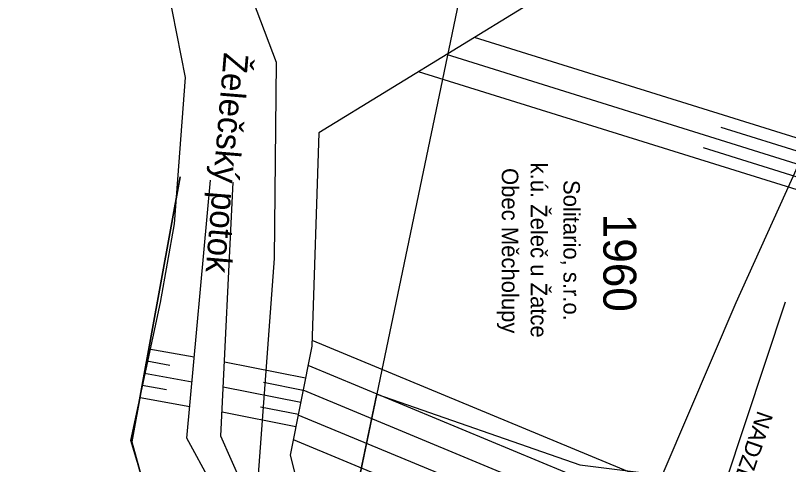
# Model space of a CAD drawing. Extents: x -801372 to -800991, y -1017235 to -1016862.
# Drawn here: x -801166.43 to -801119.55, y -1017024.1 to -1016996.85 of the extents above; entities that cross this region are included whole.
import ezdxf

# ---------------------------------------------------------------- set-up
doc = ezdxf.new("R2010")
doc.units = 0
for name, color, linetype in [('09 - stávající terén', 7, 'Continuous'), ('15 - popisy', 7, 'Continuous'), ('19 - katastr', 7, 'Continuous'), ('19b - katastr - hranice SŽDC', 7, 'Continuous'), ('19b - katastr popisy', 7, 'Continuous'), ('26 - obvod_stavby', 7, 'Continuous'), ('27 - dočasné zábory', 7, 'Continuous'), ('Vrstva 17', 7, 'Continuous'), ('Vrstva 25', 7, 'Continuous'), ('Vrstva 48 - svahy', 7, 'Continuous'), ('Vrstva 58', 7, 'Continuous')]:
    doc.layers.add(name, color=color, linetype=linetype)

msp = doc.modelspace()

# ---------------------------------------------------------------- linework, layer by layer
at = {"layer": '09 - stávající terén'}
for p, q in [((-801135.361, -1016996.195), (-801148.044, -1017003.975)), ((-801148.044, -1017003.975), (-801148.449, -1017016.921)), ((-801159.369, -1017022.733), (-801156.438, -1017006.646)), ((-801156.038, -1017022.507), (-801154.603, -1017006.835)), ((-801153.978, -1017022.39), (-801153.219, -1017006.959)), ((-801148.449, -1017016.921), (-801149.768, -1017023.543)), ((-801153.623, -1017026.95), (-801156.038, -1017022.507)), ((-801152.259, -1017026.242), (-801153.978, -1017022.39)), ((-801158.225, -1017026.81), (-801159.369, -1017022.733)), ((-801149.768, -1017023.543), (-801148.749, -1017027.534))]:
    msp.add_line(p, q, dxfattribs=at)
at = {"layer": '19 - katastr'}
for points in [[(-801202.21, -1016922.85), (-801202.84, -1016929.27), (-801199.62, -1016933.47), (-801189.32, -1016939.19), (-801185.94, -1016945.08), (-801185.46, -1016950.36), (-801182.14, -1016961.34), (-801180.53, -1016967.01), (-801177.89, -1016970.27), (-801173.07, -1016972.28), (-801168.07, -1016975.74), (-801164.36, -1016980.52), (-801157.66, -1016983.69), (-801154.36, -1016989.8), (-801150.62, -1016999.68), (-801150.74, -1017011.59), (-801151.72, -1017024.71), (-801147.17, -1017031.33)], [(-801150, -1017036.76), (-801155.85, -1017030.29), (-801158.23, -1017026.66), (-801159.44, -1017022.65), (-801157.64, -1017014.26), (-801156.79, -1017009.49), (-801156.11, -1017000.61), (-801157.69, -1016992.59), (-801165.08, -1016984.43), (-801171.01, -1016978.97), (-801178.02, -1016975.61), (-801179.3, -1016973.37), (-801181.87, -1016971.45), (-801184.14, -1016968.93), (-801188.76, -1016958.13), (-801189.39, -1016954.09), (-801189.23, -1016950.15), (-801190, -1016946.24)], [(-801150, -1017036.76), (-801155.85, -1017030.29), (-801158.23, -1017026.66), (-801159.44, -1017022.65), (-801157.64, -1017014.26), (-801156.79, -1017009.49), (-801156.11, -1017000.61), (-801157.69, -1016992.59), (-801165.08, -1016984.43), (-801171.01, -1016978.97), (-801178.02, -1016975.61), (-801179.3, -1016973.37), (-801181.87, -1016971.45), (-801184.14, -1016968.93), (-801188.76, -1016958.13), (-801189.39, -1016954.09), (-801189.23, -1016950.15), (-801190, -1016946.24)], [(-801146.24, -1016959.95), (-801138.7, -1016991.88), (-801146.17, -1017027.77)]]:
    msp.add_lwpolyline(points, dxfattribs=at)
at = {"layer": '19b - katastr - hranice SŽDC'}
msp.add_lwpolyline([(-801146.17, -1017027.77), (-801131.4, -1017034.56), (-801122.73, -1017014.27), (-801103.54, -1016971.8), (-801099.44, -1016966.34), (-801099.01, -1016964.03), (-801100.45, -1016961.93)], dxfattribs=at)
at = {"layer": '26 - obvod_stavby'}
msp.add_lwpolyline([(-801141.216, -1017053.254), (-801148.66, -1017042.443), (-801151.48, -1017039.58), (-801150.013, -1017036.785), (-801149.01, -1017037.86), (-801147.484, -1017032.446), (-801147.484, -1017032.446), (-801146.17, -1017027.77), (-801146.17, -1017027.77), (-801144.517, -1017019.826), (-801132.211, -1017024.121), (-801127.204, -1017024.741), (-801076.63, -1017043.81), (-801086.965, -1017066.29)], dxfattribs=at)
at = {"layer": '27 - dočasné zábory'}
msp.add_lwpolyline([(-801146.17, -1017027.77), (-801144.517, -1017019.826), (-801132.211, -1017024.121), (-801127.204, -1017024.741), (-801131.4, -1017034.56), (-801146.17, -1017027.77)], dxfattribs=at)
at = {"layer": 'Vrstva 17'}
for p, q in [((-801156.438, -1017006.646), (-801159.369, -1017022.733)), ((-801159.369, -1017022.733), (-801158.225, -1017026.81))]:
    msp.add_line(p, q, dxfattribs=at)
at = {"layer": 'Vrstva 25'}
msp.add_line((-801129.131, -1017042.616), (-801119.736, -1017014.228), dxfattribs=at)
at = {"layer": 'Vrstva 48 - svahy'}
for p, q in [((-801107.6, -1017007.872), (-801138.6, -1016998.182)), ((-801108.048, -1017009.304), (-801140.297, -1016999.223)), ((-801108.495, -1017010.735), (-801141.994, -1017000.264)), ((-801107.824, -1017008.588), (-801123.636, -1017003.645)), ((-801108.271, -1017010.019), (-801124.709, -1017004.881)), ((-801115.601, -1017030.203), (-801148.438, -1017016.575)), ((-801158.338, -1017017.073), (-801155.586, -1017017.574)), ((-801158.472, -1017017.811), (-801157.064, -1017018.067)), ((-801148.836, -1017018.864), (-801153.756, -1017017.884)), ((-801116.176, -1017031.588), (-801148.683, -1017018.097)), ((-801158.607, -1017018.549), (-801155.724, -1017019.074)), ((-801158.741, -1017019.286), (-801157.267, -1017019.555)), ((-801149.129, -1017020.336), (-801153.831, -1017019.399)), ((-801148.983, -1017019.6), (-801151.388, -1017019.121)), ((-801116.75, -1017032.974), (-801148.982, -1017019.597)), ((-801158.875, -1017020.024), (-801155.861, -1017020.574)), ((-801149.276, -1017021.071), (-801151.572, -1017020.614)), ((-801149.422, -1017021.807), (-801153.905, -1017020.914)), ((-801117.325, -1017034.359), (-801149.281, -1017021.097)), ((-801117.9, -1017035.744), (-801149.58, -1017022.597))]:
    msp.add_line(p, q, dxfattribs=at)

# ---------------------------------------------------------------- texts
at = {"layer": '15 - popisy'}
msp.add_text('NADZEMNÍ VEDENÍ NN', height=1, rotation=250.9519, dxfattribs=at).set_placement((-801121.42, -1017020.789))
at = {"layer": '19b - katastr popisy'}
for s, height, p in [('Obec Měcholupy', 1.00005, (-801136.94, -1017006.108)), ('k.ú. Želeč u Žatce ', 1.00005, (-801135.189, -1017005.778)), ('Solitario, s.r.o.', 1.00005, (-801133.203, -1017006.833)), ('1960', 2, (-801130.785, -1017008.884))]:
    msp.add_text(s, height=height, rotation=270, dxfattribs=at).set_placement(p)
at = {"layer": 'Vrstva 58'}
msp.add_text('Želečský potok', height=1.5, rotation=265.2321, dxfattribs=at).set_placement((-801153.787, -1016999.071))

doc.saveas('drawing.dxf')
